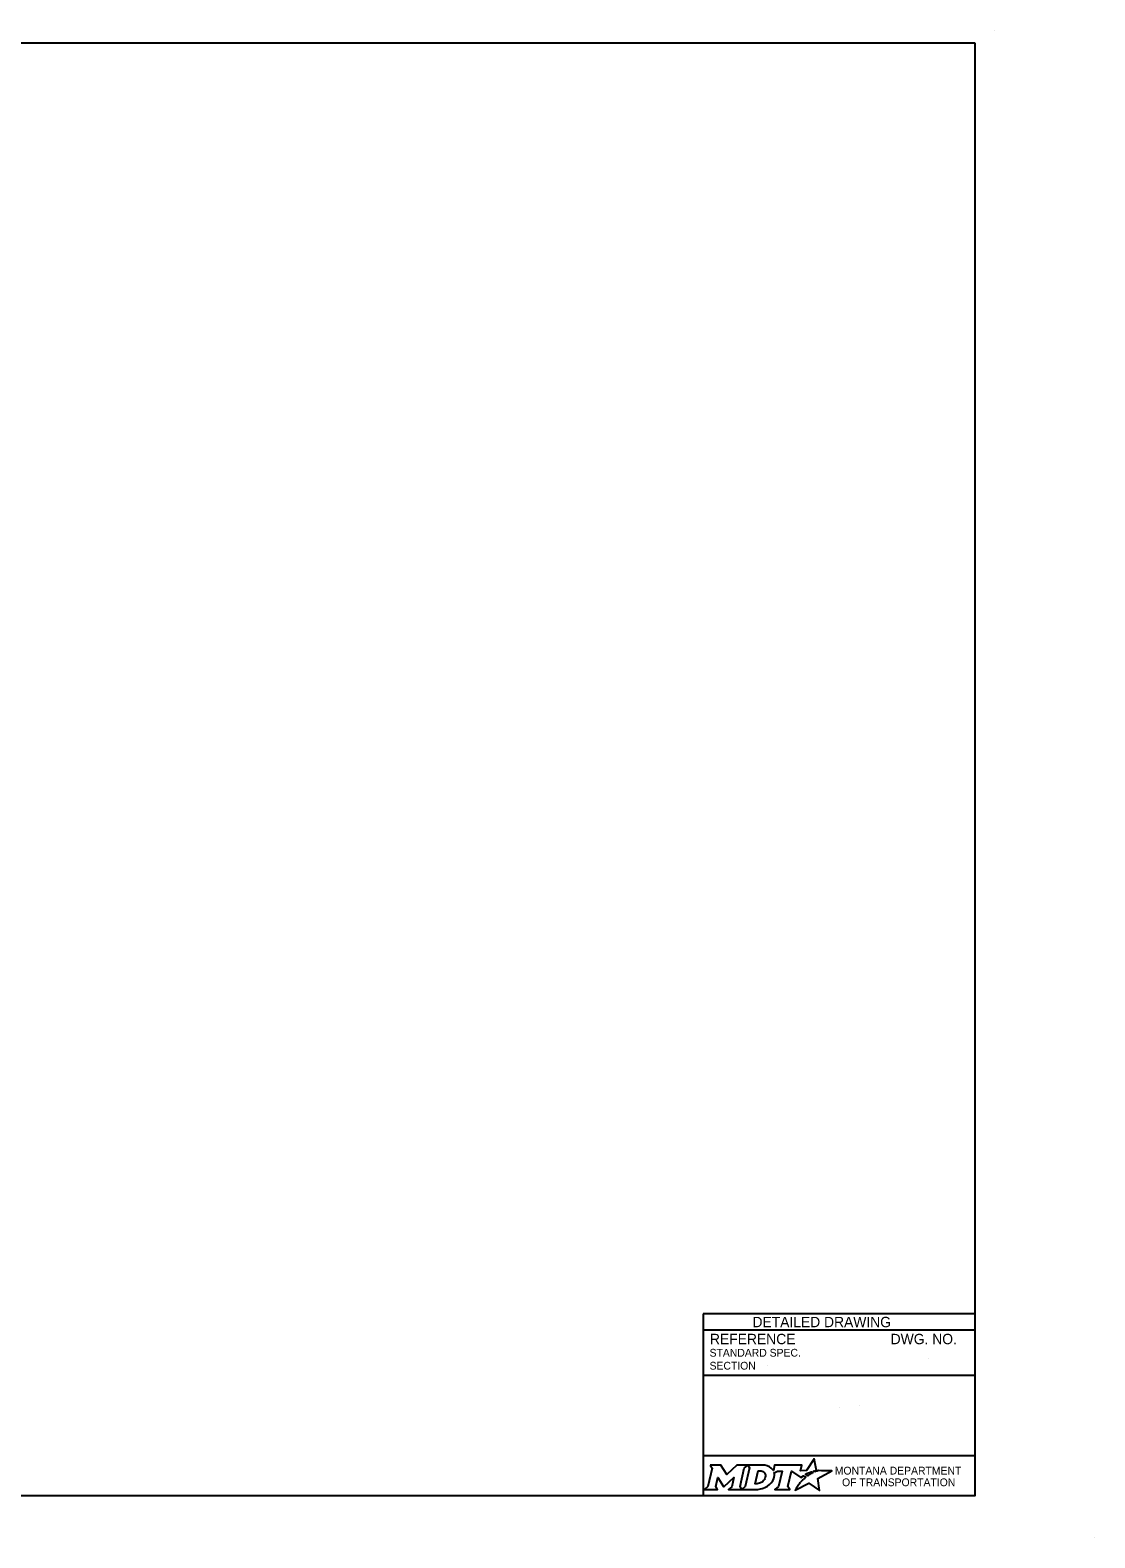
# Model space of a CAD drawing. Extents: x 49991.4 to 50021, y 49987.6 to 50011.4.
# Drawn here: x 50001.32 to 50009.54, y 49999.74 to 50011.36 of the extents above; entities that cross this region are included whole.
import ezdxf

# ---------------------------------------------------------------- set-up
doc = ezdxf.new("R2010")
doc.units = 0
for name, color, linetype in [('Default', 7, 'Continuous'), ('Level 1', 7, 'Continuous'), ('Level 2', 7, 'Continuous')]:
    doc.layers.add(name, color=color, linetype=linetype)

msp = doc.modelspace()

# ---------------------------------------------------------------- linework, layer by layer
at = {"layer": 'Default'}
msp.add_line((50007.719, 50000.757), (50007.719, 50000.757), dxfattribs=at)
at = {"layer": 'Level 1'}
for p, q in [((50008.765, 50011.363), (50008.765, 50011.363)), ((50009.537, 49999.736), (50009.537, 49999.736))]:
    msp.add_line(p, q, dxfattribs=at)
msp.add_lwpolyline([(50008.615, 50011.263), (50000.336, 50011.263), (50000.336, 50000.062), (50008.615, 50000.062)], close=True, dxfattribs=at)
at = {"layer": 'Level 2'}
for p, q in [((50008.615, 50001.462), (50006.515, 50001.462)), ((50006.515, 50001.462), (50006.515, 50000.062)), ((50008.615, 50001.337), (50006.515, 50001.337)), ((50007.009, 50001.063), (50007.009, 50001.063)), ((50008.251, 50001.122), (50008.251, 50001.122)), ((50008.615, 50000.987), (50006.515, 50000.987)), ((50007.565, 50000.738), (50007.565, 50000.738)), ((50008.615, 50000.369), (50006.515, 50000.369))]:
    msp.add_line(p, q, dxfattribs=at)
for points in [[(50007.377, 50000.245), (50007.367, 50000.25), (50007.378, 50000.253), (50007.39, 50000.255), (50007.373, 50000.345), (50007.313, 50000.254), (50007.266, 50000.253), (50007.276, 50000.297), (50007.067, 50000.297), (50007.057, 50000.255), (50007.051, 50000.263)], [(50006.57, 50000.297), (50006.584, 50000.274), (50006.551, 50000.131), (50006.525, 50000.108), (50006.627, 50000.108), (50006.613, 50000.131), (50006.629, 50000.201), (50006.673, 50000.132), (50006.678, 50000.132), (50006.753, 50000.202), (50006.737, 50000.13), (50006.712, 50000.108), (50006.814, 50000.108), (50006.8, 50000.132), (50006.833, 50000.274)], [(50006.833, 50000.274), (50006.859, 50000.297), (50006.776, 50000.297), (50006.697, 50000.224), (50006.652, 50000.297), (50006.57, 50000.297)], [(50006.972, 50000.297), (50006.859, 50000.297), (50006.873, 50000.275), (50006.839, 50000.131), (50006.814, 50000.108), (50006.925, 50000.108)], [(50006.996, 50000.211), (50006.995, 50000.203), (50006.992, 50000.193), (50006.988, 50000.185), (50006.982, 50000.178), (50006.976, 50000.171), (50006.968, 50000.164), (50006.959, 50000.16), (50006.95, 50000.156), (50006.941, 50000.154), (50006.932, 50000.153), (50006.916, 50000.153), (50006.94, 50000.253), (50006.956, 50000.253), (50006.963, 50000.252), (50006.971, 50000.25), (50006.977, 50000.247), (50006.983, 50000.243), (50006.988, 50000.238), (50006.992, 50000.232), (50006.995, 50000.226), (50006.996, 50000.218), (50006.996, 50000.215), (50006.996, 50000.211)], [(50007.064, 50000.238), (50007.088, 50000.251), (50007.125, 50000.251), (50007.097, 50000.131), (50007.069, 50000.108), (50007.185, 50000.108), (50007.168, 50000.131), (50007.196, 50000.251), (50007.268, 50000.2), (50007.289, 50000.215), (50007.309, 50000.204)], [(50007.253, 50000.148), (50007.237, 50000.124), (50007.233, 50000.116), (50007.227, 50000.107), (50007.225, 50000.103), (50007.33, 50000.156), (50007.414, 50000.101), (50007.401, 50000.194), (50007.508, 50000.252), (50007.458, 50000.253), (50007.428, 50000.253), (50007.407, 50000.254), (50007.401, 50000.252), (50007.396, 50000.251), (50007.387, 50000.249), (50007.377, 50000.245)], [(50007.327, 50000.217), (50007.324, 50000.215), (50007.306, 50000.225), (50007.316, 50000.231), (50007.32, 50000.233), (50007.329, 50000.237), (50007.335, 50000.239), (50007.343, 50000.243), (50007.35, 50000.245), (50007.362, 50000.238), (50007.358, 50000.236), (50007.353, 50000.233), (50007.349, 50000.231), (50007.344, 50000.228), (50007.342, 50000.227), (50007.339, 50000.225), (50007.337, 50000.224), (50007.334, 50000.222), (50007.332, 50000.221), (50007.329, 50000.219), (50007.327, 50000.217)], [(50006.97, 50000.116), (50006.979, 50000.118), (50006.992, 50000.124), (50007.012, 50000.135)], [(50007.267, 50000.164), (50007.267, 50000.164)]]:
    msp.add_lwpolyline(points, dxfattribs=at)
for centre, radius, start, end in [((50006.995, 50000.219), 0.0709, 339.5329, 15.8582), ((50006.951, 50000.236), 0.118, 300.9103, 339.1383)]:
    msp.add_arc(centre, radius, start, end, dxfattribs=at)
for centre, major_axis, ratio, start_param, end_param in [((50006.97, 50000.25), (0.0834, -0.0037), 0.568097, 0.61298, 1.570796), ((50007.026, 50000.257), (0.0361, -0.0295), 0.469099, 1.225588, 1.570796), ((50006.925, 50000.257), (0, 0.148), 0.987302, 3.139398, 3.456847), ((50007.26, 50000.156), (-0.00694, -0.00806), 0.008222, 0, 3.137361), ((50007.276, 50000.174), (-0.0098, -0.0102), 0.016458, 3.141593, 6.279097), ((50007.297, 50000.194), (-0.0112, -0.0097), 0.021651, 3.157348, 6.283185)]:
    msp.add_ellipse(centre, major_axis=major_axis, ratio=ratio, start_param=start_param, end_param=end_param, dxfattribs=at)

# ---------------------------------------------------------------- texts
for s, height, p in [('DETAILED DRAWING', 0.0799, (50006.896, 50001.36)), ('REFERENCE', 0.08, (50006.568, 50001.229)), ('DWG. NO.', 0.08, (50007.962, 50001.229)), ('STANDARD SPEC.', 0.06, (50006.565, 50001.133)), ('SECTION', 0.06, (50006.565, 50001.033)), ('MONTANA DEPARTMENT', 0.06, (50007.531, 50000.224)), ('OF TRANSPORTATION', 0.06, (50007.587, 50000.134))]:
    msp.add_text(s, height=height, dxfattribs=at).set_placement(p)

doc.saveas('drawing.dxf')
